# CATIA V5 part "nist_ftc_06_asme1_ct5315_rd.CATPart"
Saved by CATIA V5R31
Part number: NIST PMI FTC 06 ASME1
Revision: D
Description: NIST PMI test model downloaded from http://go.usa.gov/mGVm
Bounding box of the stored display mesh (mm): x -152.4 to 152.4, y 0 to 97.79, z -247.65 to 0
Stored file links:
  E:\users\dgn\TPS V5\Import-export annotations\Step\PMI representation 2015\NIST UC\FTC\SFA results - 21x export\nist_ftc_06_asme1_ct5315_rd.CATPart
  E:\users\dgn\TPS V5\Import-export annotations\Step\PMI representation 2015\NIST UC\nist_ftc_06_asme1_ct5240_rd.CATPart
  E:\users\dgn\TPS V5\Import-export annotations\Step\PMI representation 2015\NIST UC\CVDHoleParallelCountersink_1_TAG.CATPart
  E:\users\dgn\TPS V5\Import-export annotations\Step\PMI representation 2015\NIST UC\TS_CounterboredHole.CATPart
  E:\Download\DownloadOfCXR31rel\win_b64\resources\graphic\CATTPSGeneralTolerance.xlsx
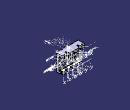
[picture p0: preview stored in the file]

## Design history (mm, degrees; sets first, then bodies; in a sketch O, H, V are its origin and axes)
TTRSSet1
f4a2d38f3ddc11d3a929006094b99c4b_11 "CATTPSSet"
Set1 "Geom_for_MBD_A_notes"
  Plane1: type Equation, A -0.57735, B -0.57735, C 0.57735, Length 229.55, RefPoint vertex [face of Pad1 from Sketch12.L1 | face of Pad1 from Sketch12.L2 | end face of Pad1], RefAxis AxisSystem5
Set2 "MBD_A"
  AxisSystem1 "F1": origin (108.585, 50.8, -209.55), X (-1, 0, 0), Y (0, 1, 0), Z (0, 0, -1)
  AxisSystem2 "F2": origin (36.195, 50.8, -209.55), X (-1, 0, 0), Y (0, 1, 0), Z (0, 0, -1)
  AxisSystem3 "F3": origin (-36.195, 50.8, -209.55), X (-1, 0, 0), Y (0, 1, 0), Z (0, 0, -1)
  AxisSystem4 "F4": origin (-108.585, 50.8, -209.55), X (-1, 0, 0), Y (0, 1, 0), Z (0, 0, -1)
  AxisSystem5 "EAB": origin (0, 0, -209.55), X (-1, 0, 0), Y (0, 0, 1), Z (0, 1, 0)
Set3 "MBD_C"
  AxisSystem6 "DCJ": origin (82.55, 31.75, 0), X (1, 0, 0), Y (0, 0, -1), Z (0, 1, 0)
  AxisSystem7 "DCK": origin (-82.55, 31.75, 0), X (1, 0, 0), Y (0, 0, -1), Z (0, 1, 0)
  AxisSystem8 "DG": origin (76.2, 31.75, -158.75), X (0, 0, -1), Y (-1, 0, 0), Z (0, 1, 0)
  AxisSystem9 "DH": origin (-76.2, 31.75, -158.75), X (0, 0, -1), Y (-1, 0, 0), Z (0, 1, 0)
  Sketch1 on face of Pocket1 from Sketch15.L6, origin (-87.885, 40.9814, 0), H (-0.4226, -0.9063, 0), V (0, 0, 1)
    line L1 (-45.8598, -31.75) -> (-45.8598, 0)
    point P1 (-45.8598, -31.75)
    reference projected point E1 (-45.8598, -31.75) from Sketch10.P5
    vertical: L1 V
    coincidence: P1 E1
  Sketch2 on face of RectPattern2, origin (87.885, 40.9814, 0), H (-0.4226, 0.9063, 0), V (0, 0, 1)
    line L1 (45.8598, -31.75) -> (45.8598, 0)
    point P1 (45.8598, -31.75)
    reference projected point E1 (45.8598, -31.75) from Sketch9.P6
    vertical: L1 V
    coincidence: P1 E1
  Sketch3 on face of RectPattern2, origin (47.7271, -22.2555, 0), H (-0.4226, -0.9063, 0), V (0, 0, 1)
    line L1 (-115.6341, -31.75) -> (-115.6341, 0)
    point P1 (-115.6341, -31.75)
    reference projected point E1 (-115.6341, -31.75) from Sketch9.P5
    vertical: L1 V
    coincidence: P1 E1
  Sketch4 on Plane6, origin (0, 66.04, 0), H (-1, 0, 0), V (0, 0, 1)
    circle A1 centre (76.2, -158.75) radius 12.7
    point P1 (76.2, -158.75)
    reference projected point E1 (76.2, -158.75) from axis of face of RectPattern6
    circle A2 centre (-76.2, -158.75) radius 12.7
    point P2 (-76.2, -158.75)
    reference projected point E2 (-76.2, -158.75) from axis of face of Hole3
    radius A1 = 12.7
    radius A2 = 12.7
    coincidence: E1 P1, E2 P2
  Sketch5 on face of RectPattern2, origin (47.7271, -22.2555, 0), H (-0.4226, -0.9063, 0), V (0, 0, 1)
    projected line E1 (-132.4556, 0) -> (-97.4233, 0) from edge [face of RectPattern2 | face of Pad1 from Sketch12.L1]
    projected line E2 (-132.4556, -31.75) -> (-97.4233, -31.75) from edge [face of Pad1 from Sketch12.L7 | face of RectPattern2]
    line L1 (-97.4233, 0) -> (-115.6341, 0)
    point P5 (-114.9395, 0)
    line L2 (-115.6341, -31.75) -> (-97.4233, -31.75)
    point P6 (-115.6341, -31.75)
    line L3 (-97.4233, 0) -> (-97.4233, -31.75)
    line L4 (-115.6341, 0) -> (-115.6341, -31.75)
    reference projected line E3 (-115.6341, -31.75) -> (-115.6341, 0) from Sketch3
    midpoint: P5 E1
    horizontal: L1 H, L2 H
    coincidence: P6 E2, E3 L4
    vertical: L3 V, L4 V
  Sketch6 on face of RectPattern2, origin (87.885, 40.9814, 0), H (-0.4226, 0.9063, 0), V (0, 0, 1)
    projected line E1 (62.6813, 0) -> (27.6491, 0) from edge [face of Pad1 from Sketch12.L1 | face of RectPattern2]
    projected line E2 (45.8598, 0) -> (27.6491, 0) from edge [face of Pad1 from Sketch12.L1 | face of RectPattern2]
    projected line E3 (27.6491, -31.75) -> (27.6491, 0) from edge [face of RectPattern2 | face of RectPattern2]
    projected line E4 (27.6491, -31.75) -> (62.6813, -31.75) from edge [face of Pad1 from Sketch12.L7 | face of RectPattern2]
    projected line E5 (27.6491, -31.75) -> (45.8598, -31.75) from edge [face of Pad1 from Sketch12.L7 | face of RectPattern2]
    projected line E6 (45.8598, -31.75) -> (45.8598, 0) from Sketch2.L1
  Sketch7 on face of Pocket1 from Sketch15.L6, origin (-87.885, 40.9814, 0), H (-0.4226, -0.9063, 0), V (0, 0, 1)
    projected line E1 (-62.6813, 0) -> (-27.6491, 0) from edge [face of Pocket1 from Sketch15.L6 | face of Pad1 from Sketch12.L1]
    projected line E2 (-45.8598, 0) -> (-27.6491, 0) from edge [face of Pocket1 from Sketch15.L6 | face of Pad1 from Sketch12.L1]
    projected line E3 (-62.6813, -31.75) -> (-27.6491, -31.75) from edge [face of Pad1 from Sketch12.L7 | face of Pocket1 from Sketch15.L6]
    projected line E4 (-45.8598, -31.75) -> (-27.6491, -31.75) from edge [face of Pad1 from Sketch12.L7 | face of Pocket1 from Sketch15.L6]
    projected line E5 (-27.6491, -31.75) -> (-27.6491, 0) from edge [face of Pocket1 from Sketch15.L5 | face of Pocket1 from Sketch15.L6]
    projected line E6 (-45.8598, -31.75) -> (-45.8598, 0) from Sketch1.L1
  Sketch8 on face of Pocket1 from Sketch15.L1, origin (-47.7271, -22.2555, 0), H (-0.4226, 0.9063, 0), V (0, 0, 1)
    projected line E1 (97.4233, -31.75) -> (132.4556, -31.75) from edge [face of Pad1 from Sketch12.L7 | face of Pocket1 from Sketch15.L1]
    projected line E2 (97.4233, -31.75) -> (115.6341, -31.75) from edge [face of Pad1 from Sketch12.L7 | face of Pocket1 from Sketch15.L1]
    projected line E3 (97.4233, -31.75) -> (97.4233, 0) from edge [face of Pocket1 from Sketch15.L1 | face of Pocket1 from Sketch15.L2]
    projected line E4 (132.4556, 0) -> (97.4233, 0) from edge [face of Pad1 from Sketch12.L1 | face of Pocket1 from Sketch15.L1]
    projected line E5 (115.6341, 0) -> (97.4233, 0) from edge [face of Pad1 from Sketch12.L1 | face of Pocket1 from Sketch15.L1]
    projected line E6 (115.6341, -31.75) -> (115.6341, 0) from Sketch11.L1
    construction line L1 through (0, 0) direction (0, 1)
  Sketch9 on face of Pad1 from Sketch12.L7, origin (0, 0, -31.75), H (1, 0, 0), V (0, -1, 0)
    projected line E1 (103.7053, -97.79) -> (88.9, -66.04) from edge [face of Pad1 from Sketch12.L7 | face of RectPattern2]
    projected line E2 (76.2, -66.04) -> (61.3947, -97.79) from edge [face of Pad1 from Sketch12.L7 | face of RectPattern2]
    line L1 (88.9, -66.04) -> (76.2, -66.04)
    line L2 (96.5962, -82.5446) -> (68.5038, -82.5446)
    point P5 (96.5962, -82.5446)
    point P6 (68.5038, -82.5446)
    point P7 (96.5962, -82.5446)
    point P8 (68.5038, -82.5446)
    length L2 = 28.0924
    horizontal: L1 H, L2 H
    coincidence: P5 E1, P6 E2, P7 P5, P8 P6
  Sketch10 on face of Pad1 from Sketch12.L7, origin (0, 0, -31.75), H (1, 0, 0), V (0, -1, 0)
    projected line E1 (-61.3947, -97.79) -> (-76.2, -66.04) from edge [face of Pad1 from Sketch12.L7 | face of Pocket1 from Sketch15.L6]
    projected line E2 (-88.9, -66.04) -> (-103.7053, -97.79) from edge [face of Pad1 from Sketch12.L7 | face of Pocket1 from Sketch15.L1]
    line L1 (-76.2, -66.04) -> (-88.9, -66.04)
    line L2 (-68.5038, -82.5446) -> (-96.5962, -82.5446)
    point P5 (-68.5038, -82.5446)
    point P6 (-96.5962, -82.5446)
    point P7 (-68.5038, -82.5446)
    point P8 (-96.5962, -82.5446)
    length L2 = 28.0924
    horizontal: L1 H, L2 H
    coincidence: P5 E1, P7 P5, P6 E2, P8 P6
  Sketch11 on face of Pocket1 from Sketch15.L1, origin (-47.7271, -22.2555, 0), H (-0.4226, 0.9063, 0), V (0, 0, 1)
    line L1 (115.6341, -31.75) -> (115.6341, 0)
    point P1 (115.6341, -31.75)
    reference projected point E1 (115.6341, -31.75) from Sketch10.P6
    vertical: L1 V
    coincidence: P1 E1
  Line1 to Line4: stored without definition
Set4 "MBD_A_B_C"
  AxisSystem10 "DBC": origin (0, 31.75, 0), X (1, 0, 0), Y (0, 0, -1), Z (0, 1, 0)
  AxisSystem11 "ABC": origin (0, 0, 0), X (1, 0, 0), Y (0, 0, -1), Z (0, 1, 0)
Set5
  Plane2: type Offset, RefPlane xy-plane, Offset 247.65, reversed
  Plane3: type Offset, RefPlane zx-plane, Offset 46.99
  Plane4: type Offset, RefPlane yz-plane, Offset 76.2
  Plane5: type Offset, RefPlane yz-plane, Offset 114.3
  Point1: type OnCurve, Support edge [face of Pad1 from Sketch12.L7 | face of Pocket1 from Sketch15.L1], Length 18.2093
  Point2: type OnCurve, Support edge [face of Pad1 from Sketch12.L7 | face of Pocket1 from Sketch15.L6], Length 18.2093
  Point3: type OnCurve, Support edge [face of Pad1 from Sketch12.L7 | face of RectPattern2], Length 18.2093
  Point4: type OnCurve, Support edge [face of Pad1 from Sketch12.L7 | face of RectPattern2], Length 18.2093
  Plane6: type Offset, RefPlane zx-plane, Offset 66.04
  Plane7: type Angle, RefPlane xy-plane, Direction edge [face of Pad1 from Sketch12.L2 | face of Pad1 from Sketch12.L1], Angle 45
  Point5: type OnCurve, Support edge [face of Pad1 from Sketch12.L2 | face of Pad1 from Sketch12.L1], Length 152.4
  Point6: type OnPlane, Support face of Pad1 from Sketch12.L6, H 0, V 0, Direction (-1, 0, 0)
  Point7: type OnCurve, Support edge [face of Fillet1 | face of Pad1 from Sketch12.L6], RefPoint {extremum Reference edge [face of Fillet1 | face of Pad1 from Sketch12.L6], Direction (1, 2, 3)}, Length 65.977
  Point8: type OnCurve, Support edge [face of Fillet1 | face of Pad1 from Sketch12.L6], RefPoint {extremum Reference edge [face of Fillet1 | face of Pad1 from Sketch12.L6], Direction (1, 2, 3)}, Length 65.9892
  Point9: type OnPlane, Support face of Pad1 from Sketch12.L1, H 82.55, V 31.75, Direction (1, 0, 0)
  Point10: type OnPlane, Support face of Pad1 from Sketch12.L1, H -82.55, V 31.75, Direction (1, 0, 0)
  Plane8: type Offset, RefPlane face of Pad1 from Sketch12.L2, Offset 82.55
  Plane9: type Offset, RefPlane face of Pad1 from Sketch12.L2, Offset 66.04
  Point11: type OnSurface, Support face of Fillet1, Length 0, Direction (-0.9567, 0.021, -0.2904)
  Plane10: type Offset, RefPlane face of Pad1 from Sketch12.L1, Offset 107.95
  Point12: type OnPlane, Support face of Pad1 from Sketch12.L6, H -76.2, V -158.75, Direction (-1, 0, 0)
  Point13: type OnPlane, Support face of Pad1 from Sketch12.L6, H 76.2, V -158.75, Direction (-1, 0, 0)
  Point14: type OnPlane, Support face of Pad1 from Sketch12.L2, H 0, V -209.55, Direction (1, 0, 0)
  Plane11: type Offset, RefPlane face of Pad1 from Sketch12.L8, Offset 0, reversed
  Point15 to Point18: stored without definition
Body1 (main body)
  Sketch12 on yz-plane, origin (0, 0, 0), H (0, 1, 0), V (0, 0, 1)
    point P1 (97.79, 0)
    line L1 (97.79, 0) -> (0, 0)
    line L2 (0, 0) -> (0, -234.95)
    line L3 (0, -234.95) -> (50.8, -234.95)
    line L4 (50.8, -234.95) -> (50.8, -209.55)
    line L5 (50.8, -209.55) -> (31.75, -209.55)
    line L6 (31.75, -209.55) -> (31.75, -31.75)
    line L7 (31.75, -31.75) -> (97.79, -31.75)
    line L8 (97.79, -31.75) -> (97.79, 0)
    length L2 = 234.95
    distance L1 L5 = 209.55
    distance L1 L7 = 31.75
    distance L2 L6 = 31.75
    distance L4 L2 = 50.8
    distance L2 L8 = 97.79
    coincidence: P1 H
    horizontal: L1 H, L3 H, L5 H, L7 H
    vertical: L2 V, L4 V, L6 V, L8 V
  Pad1: profile Sketch12, direction (1, 0, 0), length 152.4, mirrored extent
  Sketch13 on yz-plane, origin (0, 0, 0), H (0, 1, 0), V (0, 0, 1)
    line L1 (97.79, -31.75) -> (46.99, -133.35)
    point P1 (97.79, -31.75)
    point P2 (46.99, -133.35)
    line L2 (46.99, -133.35) -> (31.75, -133.35)
    point P3 (31.75, -133.35)
    reference projected point E1 (97.79, -31.75) from vertex [face of Pad1 from Sketch12.L8 | end face of Pad1 | face of Pad1 from Sketch12.L7]
    reference projected point E2 (97.79, -31.75) from vertex [face of Pad1 from Sketch12.L8 | end face of Pad1 | face of Pad1 from Sketch12.L7]
    reference projected line E3 (31.75, -31.75) -> (97.79, -31.75) from edge [face of Pad1 from Sketch12.L7 | end face of Pad1]
    reference projected line E4 (97.79, -31.75) -> (97.79, 0) from edge [face of Pad1 from Sketch12.L8 | end face of Pad1]
    reference intersected line E5 (31.75, -31.75) -> (31.75, -209.55) from face of Pad1 from Sketch12.L6
    distance E3 L2 = 101.6
    distance P2 E4 = 50.8
    coincidence: E1 L1, E2 P1, E5 P3
  Stiffener1: ExtendedProfile Sketch13, ThicknessTop 0, ThicknessValue 25.4
  Sketch14 on Plane2, origin (0, 0, -247.65), H (1, 0, 0), V (0, 1, 0)
    circle A1 centre (108.585, 50.8) radius 22.225
    point P1 (108.585, 50.8)
    reference projected line E1 (-152.4, 0) -> (152.4, 0) from edge [face of Pad1 from Sketch12.L3 | face of Pad1 from Sketch12.L2]
    reference intersected line E2 through (152.4, 0) direction (0, 1) from end face of Pad1
    distance P1 E1 = 50.8
    radius A1 = 22.225
    distance E2 P1 = 43.815
  Pad2: profile Sketch14, direction (0, 0, 1), length 38.1
  RectPattern1: of Pad2, direction 1 instances 4, spacing 72.39, along edge [face of Pad1 from Sketch12.L4 | face of Pad1 from Sketch12.L3] reversed
  Sketch15 on face of Pad1 from Sketch12.L7, origin (0, 0, -31.75), H (1, 0, 0), V (0, -1, 0)
    line L1 (-103.7053, -97.79) -> (-88.9, -66.04)
    point P1 (-88.9, -66.04)
    line L2 (-88.9, -66.04) -> (-88.9, -52.07)
    line L3 (-88.9, -52.07) -> (-76.2, -52.07)
    reference intersected line E1 (-152.4, 0) -> (152.4, 0) from face of Pad1 from Sketch12.L2
    axis line L4 (-82.55, -52.07) -> (-82.55, -133.5251)
    reference intersected line E2 (-152.4, 0) -> (152.4, 0) from face of Pad1 from Sketch12.L2
    point P7 (-76.2, -66.04)
    line L5 (-76.2, -66.04) -> (-76.2, -52.07)
    line L6 (-61.3947, -97.79) -> (-76.2, -66.04)
    reference intersected line E3 through (0, 0) direction (0, 1) from yz-plane
    projected line E4 (-152.4, -97.79) -> (-12.7, -97.79) from edge [face of Pad1 from Sketch12.L8 | face of Pad1 from Sketch12.L7]
    projected line E5 (-103.7053, -97.79) -> (-61.3947, -97.79) from edge [face of Pad1 from Sketch12.L8 | face of Pad1 from Sketch12.L7]
    distance E1 L3 = 52.07
    length L3 = 12.7
    distance L2 L4 = 6.35
    distance E2 P1 = 66.04
    distance E2 P7 = 66.04
    distance L5 L4 = 6.35
    angle L1 L6 = 50
    distance E3 L4 = 82.55
    angle L1 L4 = 25
  Pocket1: profile Sketch15, direction (0, 0, 1), through (limit type 6)
  RectPattern2: of Pocket1, direction 1 instances 2, spacing 165.1, along edge [face of Pad1 from Sketch12.L8 | face of Pad1 from Sketch12.L7]
  Sketch16 on Plane3, origin (0, 46.99, 0), H (0, 0, 1), V (1, 0, 0)
    circle A1 centre (-158.75, 76.2) radius 15.875
    point P1 (-158.75, 76.2)
    reference projected line E1 (0, -152.4) -> (0, 152.4) from edge [face of Pad1 from Sketch12.L1 | face of Pad1 from Sketch12.L8]
    reference intersected line E2 through (0, 0) direction (-1, 0) from yz-plane
    radius A1 = 15.875
    distance E1 P1 = 158.75
    distance E2 P1 = 76.2
  Pad3: profile Sketch16, direction (0, -1, 0), up to face of Pad1 from Sketch12.L6
  Sketch17 on Plane4, origin (76.2, 0, 0), H (0, 1, 0), V (0, 0, 1)
    axis line L1 (47.3647, -158.75) -> (174.207, -158.75)
    reference intersected line E1 (0, 0) -> (97.79, 0) from face of Pad1 from Sketch12.L1
    point P3 (46.99, -174.625)
    line L2 (46.99, -174.625) -> (85.09, -168.275)
    line L3 (85.09, -168.275) -> (85.09, -158.75)
    line L4 (85.09, -158.75) -> (46.99, -158.75)
    reference intersected line E2 (0, -234.95) -> (0, 0) from face of Pad1 from Sketch12.L2
    projected line E3 (46.99, -142.875) -> (46.99, -174.625) from edge [face of Pad3 from Sketch16.A1 | start face of Pad3]
    projected line E4 (46.99, -158.75) -> (46.99, -174.625) from edge [face of Pad3 from Sketch16.A1 | start face of Pad3]
    point P7 (46.99, -174.625)
    distance E1 L1 = 158.75
    distance L3 E2 = 85.09
    length L3 = 9.525
    coincidence: P3 P7, L1 L4
  Shaft1: profile Sketch17, axis Sketch17.L1, angle 360
  Sketch18 on Plane5, origin (114.3, 0, 0), H (0, 1, 0), V (0, 0, 1)
    axis line L1 (-156.5, -107.95) -> (163.5, -107.95)
    arc A1 centre (63.5, -107.95) radius 15.875 from (79.375, -107.95) to (47.625, -107.95) ccw
    point P3 (63.5, -107.95)
    reference projected line E1 (97.79, 0) -> (0, 0) from edge [face of Pad1 from Sketch12.L1 | end face of Pad1]
    reference projected line E2 (0, 0) -> (0, -234.95) from edge [face of Pad1 from Sketch12.L2 | end face of Pad1]
    distance P3 E1 = 107.95
    distance E2 P3 = 63.5
    radius A1 = 15.875
    coincidence: P3 L1
  Shaft2: profile Sketch18, axis Sketch18.L1, angle 360
  Sketch19 on face of Pad1 from Sketch12.L6, origin (0, 31.75, 0), H (-1, 0, 0), V (0, 0, 1)
    circle A1 centre (-114.3, -107.95) radius 11.43
    point P1 (-114.3, -107.95)
    reference intersected line E1 (-152.4, 0) -> (152.4, 0) from face of Pad1 from Sketch12.L1
    reference intersected line E2 through (0, 0) direction (0, -1) from yz-plane
    distance P1 E1 = 107.95
    distance P1 E2 = 114.3
    radius A1 = 11.43
  Pad4: profile Sketch19, direction (0, 1, 0), up to face of Shaft2 from Sketch18.A1
  Sketch20 on face of Pad1 from Sketch12.L7, origin (129.0197, 80.9562, -31.75), H (1, 0, 0), V (0, -1, 0)
    point P1 (-2.0197, 2.2162)
    reference intersected line E1 through (-129.0197, 0) direction (0, 1) from yz-plane
    reference intersected line E2 (23.3803, -16.8338) -> (-281.4197, -16.8338) from face of Pad1 from Sketch12.L8
    distance E1 P1 = 127
    distance P1 E2 = 19.05
  Hole1: placed by Sketch20, at (127, 78.74, -31.75) direction (0, 0, 1), diameter 14.2875, through (limit type 6), counterbore diameter 20.6375, counterbore depth 14.2875
  RectPattern3: of Hole1, direction 1 instances 2, spacing 254, along edge [face of Pad1 from Sketch12.L8 | face of Pad1 from Sketch12.L7] reversed
  Sketch21 on face of Pad1 from Sketch12.L6, origin (123.0782, 31.75, -62.8696), H (1, 0, 0), V (0, 0, -1)
    point P1 (10.2718, -5.7196)
    reference projected line E1 (-275.4782, -62.8696) -> (29.3218, -62.8696) from edge [face of Pad1 from Sketch12.L1 | face of Pad1 from Sketch12.L8]
    reference intersected line E2 through (-123.0782, 0) direction (0, 1) from yz-plane
    distance E1 P1 = 57.15
    distance E2 P1 = 133.35
  Hole2: placed by Sketch21, at (133.35, 31.75, -57.15) direction (0, -1, 0), diameter 10.541, through (limit type 6), counterbore diameter 15.875, counterbore depth 12.7
  RectPattern4: of Hole2, direction 1 instances 2, spacing 266.7, along edge [face of Pad1 from Sketch12.L8 | face of Pad1 from Sketch12.L7] reversed, direction 2 instances 2, spacing 127, along edge [face of Pad1 from Sketch12.L6 | end face of Pad1] reversed
  RectPattern5: of Pad3, Sketch16, Shaft1, Sketch17, direction 1 instances 2, spacing 152.4, along edge [face of Pad1 from Sketch12.L8 | face of Pad1 from Sketch12.L7] reversed, direction 2 instances 2, spacing 127
  Sketch22 on face of Shaft1 from Sketch17.L3, origin (76.2, 85.09, -158.75), H (1, 0, 0), V (0, 0, -1)
    point P1 (0, 0)
    coincidence: P1 O
  Hole3: placed by Sketch22, at (76.2, 85.09, -158.75) direction (0, -1, 0), diameter 6.35, depth 12.7, V-bottom angle 118
  RectPattern6: of Hole3, direction 1 instances 2, spacing 152.4, along edge [face of Pad1 from Sketch12.L4 | face of Pad1 from Sketch12.L3] reversed, direction 2 instances 2, spacing 127
  Fillet1: radius 3.175, on edge [face of Pad1 from Sketch12.L7 | face of Pad1 from Sketch12.L6] (x2); edge [face of Stiffener1 | face of Pad1 from Sketch12.L7]; edge [face of Pad1 from Sketch12.L6 | face of Stiffener1]; edge [face of Stiffener1 from Sketch13.L2 | face of Pad1 from Sketch12.L6]; edge [face of Stiffener1 | face of Pad1 from Sketch12.L6]; edge [face of Pad1 from Sketch12.L7 | face of Stiffener1]; edge [face of Pad1 from Sketch12.L6 | face of RectPattern5]; edge [face of Pad1 from Sketch12.L6 | face of Pad3 from Sketch16.A1]; edge [face of Pad1 from Sketch12.L6 | face of RectPattern1]; edge [face of Pad1 from Sketch12.L4 | face of Pad2 from Sketch14.A1]; edge [face of Pad2 from Sketch14.A1 | face of Pad1 from Sketch12.L4]; edge [face of RectPattern1 | face of Pad1 from Sketch12.L4] (x3); edge [face of Pad1 from Sketch12.L4 | face of RectPattern1] (x3)
  Sketch23 on face of Pad1 from Sketch12.L8, origin (0, 97.79, 0), H (-1, 0, 0), V (0, 0, 1)
    arc A1 centre (0, -15.875) radius 12.7 from (0, -28.575) to (0, -3.175) ccw
    point P1 (0, -15.875)
    reference intersected line E1 through (0, 0) direction (0, -1) from yz-plane
    reference intersected line E2 (152.4, -31.75) -> (-152.4, -31.75) from face of Pad1 from Sketch12.L7
    line L1 (0, -3.175) -> (0, -28.575)
    radius A1 = 12.7
    distance E2 P1 = 15.875
    coincidence: E1 P1, P1 L1
    vertical: L1 V
  Fillet2: radius 12.7, on edge [start face of Pad1 | face of Pad1 from Sketch12.L8]; edge [face of Pad1 from Sketch12.L8 | end face of Pad1]
  Groove1: profile Sketch23, axis Sketch23.L1, angle 360
  Sketch24 on Plane10, origin (0, 97.79, -107.95), H (0, 1, 0), V (1, 0, 0)
    line L1 (-66.04, -114.3) -> (-18.415, -114.3)
    point P1 (-162.8215, -114.3)
    point P2 (-2.54, -114.3)
    line L2 (-66.04, -114.3) -> (-66.04, -125.73)
    line L3 (-66.04, -125.73) -> (-45.3068, -125.73)
    arc A1 centre (-34.29, -114.3) radius 15.875 from (-45.3068, -125.73) to (-18.415, -114.3) ccw
    point P5 (-34.29, -114.3)
    reference intersected line E1 (-66.04, 152.4) -> (-66.04, -152.4) from face of Pad1 from Sketch12.L6
    reference intersected line E2 through (0, 0) direction (-1, 0) from yz-plane
    reference intersected line E3 (-97.79, -152.4) -> (-97.79, 152.4) from face of Pad1 from Sketch12.L2
    radius A1 = 15.875
    distance E2 L1 = 114.3
    distance L1 L3 = 11.43
    distance P5 E3 = 63.5
    horizontal: L1 H, L3 H
    vertical: L2 V
    coincidence: E1 L2, P1 L1, L1 P5
  Shaft3: profile Sketch24, axis Sketch24.L1, angle 360
  Fillet3: radius 3.175, on edge [face of Pad4 from Sketch19.A1 | face of Shaft2 from Sketch18.A1]; edge [face of Pad1 from Sketch12.L6 | face of Pad4 from Sketch19.A1]
  Fillet4: radius 3.175, on edge [face of Shaft3 from Sketch24.A1 | face of Shaft3 from Sketch24.L3]; edge [face of Shaft3 from Sketch24.L3 | face of Pad1 from Sketch12.L6]
  Sketch25 "Main View" on face of Pad1 from Sketch12.L3, origin (0, 0, -234.95), H (-1, 0, 0), V (0, 1, 0)
    point P1 (-27.9401, 6.35)
    point P2 (-14.4332, 7.6694)
    point P3 (-8.1701, 9.8671)
    point P4 (-3.0267, 10.5457)
    point P5 (-1.9341, 9.4532)
    point P6 (-24.8376, 6.35)
    point P7 (-27.9401, 6.35)
    point P8 (-24.8376, 17.5935)
    point P9 (-24.8376, 6.35)
    point P10 (-23.9004, 17.959)
    point P11 (-24.8376, 17.5935)
    point P12 (-14.4332, 7.6694)
    point P13 (-23.9004, 17.959)
    point P14 (-8.1701, 21.35)
    point P15 (-8.1701, 9.8671)
    point P16 (-11.3024, 21.35)
    point P17 (-8.1701, 21.35)
    point P18 (-11.3024, 9.9419)
    point P19 (-11.3024, 21.35)
    point P20 (-12.02, 9.6257)
    point P21 (-11.3024, 9.9419)
    point P22 (-22.2849, 20.7261)
    point P23 (-12.02, 9.6257)
    point P24 (-22.2849, 20.7261)
    point P25 (-27.9401, 18.5121)
    point P26 (-27.9401, 6.35)
    point P27 (-27.9401, 18.5121)
    point P28 (-3.0267, 21.35)
    point P29 (-6.159, 21.35)
    point P30 (-3.0267, 10.5457)
    point P31 (-3.0267, 21.35)
    point P32 (12.7773, 9.4532)
    point P33 (-1.9341, 9.4532)
    point P34 (12.7773, 9.4532)
    point P35 (12.7198, 12.2696)
    point P36 (3.668, 12.2696)
    point P37 (12.7198, 12.2696)
    point P38 (3.3241, 21.35)
    point P39 (3.668, 12.2696)
    point P40 (28.9273, 21.35)
    point P41 (3.3241, 21.35)
    point P42 (28.9273, 18.189)
    point P43 (28.9273, 21.35)
    point P44 (22.5181, 18.189)
    point P45 (28.9273, 18.189)
    point P46 (22.5181, 6.35)
    point P47 (22.5181, 18.189)
    point P48 (19.4156, 6.35)
    point P49 (22.5181, 6.35)
    point P50 (19.4156, 18.189)
    point P51 (19.4156, 6.35)
    point P52 (3.7255, 18.189)
    point P53 (19.4156, 18.189)
    point P54 (3.7255, 18.189)
    point P55 (3.6105, 15.3729)
    point P56 (13.2373, 15.3729)
    point P57 (3.6105, 15.3729)
    point P58 (13.2373, 6.35)
    point P59 (13.2373, 15.3729)
    point P60 (-1.9632, 6.35)
    point P61 (13.2373, 6.35)
    point P62 (-6.159, 10.5457)
    point P63 (-1.9632, 6.35)
    point P64 (-6.159, 21.35)
    point P65 (-6.159, 10.5457)
    line L1 (-6.159, 21.35) -> (-6.159, 10.5457)
    arc A1 centre (-1.9632, 10.5457) radius 4.1957 from (-6.159, 10.5457) to (-1.9632, 6.35) ccw
    line L2 (-1.9632, 6.35) -> (13.2373, 6.35)
    arc A2 centre (12.5188, 10.8615) radius 4.5683 from (13.2373, 6.35) to (13.2373, 15.3729) ccw
    line L3 (13.2373, 15.3729) -> (3.6105, 15.3729)
    arc A3 centre (3.6105, 16.7833) radius 1.4104 from (3.7255, 18.189) to (3.6105, 15.3729) ccw
    line L4 (3.7255, 18.189) -> (19.4156, 18.189)
    line L5 (19.4156, 18.189) -> (19.4156, 6.35)
    line L6 (19.4156, 6.35) -> (22.5181, 6.35)
    line L7 (22.5181, 6.35) -> (22.5181, 18.189)
    line L8 (22.5181, 18.189) -> (28.9273, 18.189)
    line L9 (28.9273, 18.189) -> (28.9273, 21.35)
    line L10 (28.9273, 21.35) -> (3.3241, 21.35)
    arc A4 centre (3.3241, 16.8033) radius 4.5467 from (3.3241, 21.35) to (3.668, 12.2696) ccw
    line L11 (3.668, 12.2696) -> (12.7198, 12.2696)
    arc A5 centre (12.5971, 10.8583) radius 1.4166 from (12.7773, 9.4532) to (12.7198, 12.2696) ccw
    line L12 (12.7773, 9.4532) -> (-1.9341, 9.4532)
    line L13 (-3.0267, 10.5457) -> (-3.0267, 21.35)
    line L14 (-3.0267, 21.35) -> (-6.159, 21.35)
    line L15 (-27.9401, 6.35) -> (-27.9401, 18.5121)
    arc A6 centre (-24.6791, 18.5121) radius 3.261 from (-22.2849, 20.7261) to (-27.9401, 18.5121) ccw
    line L16 (-22.2849, 20.7261) -> (-12.02, 9.6257)
    arc A7 centre (-11.7156, 9.9072) radius 0.4146 from (-12.02, 9.6257) to (-11.3024, 9.9419) ccw
    line L17 (-11.3024, 9.9419) -> (-11.3024, 21.35)
    line L18 (-11.3024, 21.35) -> (-8.1701, 21.35)
    line L19 (-8.1701, 21.35) -> (-8.1701, 9.8671)
    line L20 (-14.4332, 7.6694) -> (-23.9004, 17.959)
    arc A8 centre (-24.2977, 17.5935) radius 0.5399 from (-23.9004, 17.959) to (-24.8376, 17.5935) ccw
    line L21 (-24.8376, 17.5935) -> (-24.8376, 6.35)
    line L22 (-24.8376, 6.35) -> (-27.9401, 6.35)
    arc A9 centre (-1.9341, 10.5457) radius 1.0926 from (-3.0267, 10.5457) to (-1.9341, 9.4532) ccw
    arc A10 centre (-11.6873, 9.8671) radius 3.5171 from (-14.4332, 7.6694) to (-8.1701, 9.8671) ccw
    distance P1 H = 6.35
    distance P1 V = 27.94
    fix: P2, P3, P4, P5, P6, P8, P9, P10, P11, P12, P13, P14, P15, P16, P17, P18, P19, P20, P21, P22, P23, P24, P25, P27, P28, P29, P30, P31, P32, P33, P34, P35, P36, P37, P38, P39, P40, P41, P42, P43, P44, P45, P46, P47, P48, P49, P50, P51, P52, P53, P54, P55, P56, P57, P58, P59, P60, P61, P62, P63, P64, P65, P1, P7, L1, A1, L2, A2, L3, A3, L4, L5, L6, L7, L8, L9, L10, A4, L11, A5, L12, L13, L14, L15, A6, L16, A7, L17, L18, L19, L20, A8, L21, L22, A9, A10, P26
  Pocket2: profile Sketch25, direction (0, 0, 1), length 2.54
  UdfFeature1 "Counterbored Hole": UdfShapeIn Pocket2, UdfInputSpec1 AxisSystem12, UdfInputSpec2 Project1, UdfInputSpec3 Intersect1, DB 7.1374, T 40.64 {= Body2.Offset + (Sketch26.length(L2) * (Body2.Offset / Body2.Offset))}, DFS 10.16, TFS 10.414
  UdfFeature2 "Counterbored Hole": UdfShapeIn UdfFeature1, UdfInputSpec1 AxisSystem14, UdfInputSpec2 Project2, UdfInputSpec3 Intersect2, DB 7.1374, T 40.64 {= Body3.Offset + (Sketch27.length(L2) * (Body3.Offset / Body3.Offset))}, DFS 10.16, TFS 10.414
  UdfFeature3 "Counterbored Hole": UdfShapeIn UdfFeature2, UdfInputSpec1 AxisSystem16, UdfInputSpec2 Project3, UdfInputSpec3 Intersect3, DB 7.1374, T 40.64 {= Body4.Offset + (Sketch28.length(L2) * (Body4.Offset / Body4.Offset))}, DFS 10.16, TFS 10.414
  UdfFeature4 "Counterbored Hole": UdfShapeIn UdfFeature3, UdfInputSpec1 AxisSystem18, UdfInputSpec2 Project4, UdfInputSpec3 Intersect4, DB 7.1374, T 40.64 {= Body5.Offset + (Sketch29.length(L2) * (Body5.Offset / Body5.Offset))}, DFS 10.16, TFS 10.414
Body2 "UDF_Body"
  AxisSystem12 "MainAxisSystem": origin (108.585, 50.8, -250.19), X (-0.9916, -0.1291, 0), Y (-0.1291, 0.9916, 0), Z (0, 0, -1)
  Project1 "Project": ToProject vertex [YZ plane of AxisSystem12 | ZX plane of AxisSystem12 | XY plane of AxisSystem12], Support face of RectPattern1
  Intersect1 "Intersect": ToIntersect1 edge [ZX plane of AxisSystem12 | YZ plane of AxisSystem12], ToIntersect2 face of RectPattern1
  Sketch26 "MainProfileSketch" on ZX plane of AxisSystem12, origin (108.585, 50.8, -250.19), H (0.9916, 0.1291, 0), V (0, 0, -1)
    axis line L1 (0, 0) -> (0, -40.64)
    line L2 (0, -40.64) -> (3.5687, -40.64)
    point P3 (3.5687, -40.64)
    line L3 (3.5687, -40.64) -> (3.5687, -10.414)
    line L4 (5.08, -2) -> (7.08, 0)
    point P4 (7.08, 0)
    line L5 (7.08, 0) -> (7.08, 0)
    line L6 (7.08, 0) -> (7.08, 0)
    line L7 (7.08, 0) -> (0, 0)
    construction line L8 (7.08, 0) -> (0, 0)
    reference projected line E1 through (0, 0) direction (-1, 0) from edge [XY plane of AxisSystem12 | ZX plane of AxisSystem12]
    reference projected line E2 through (0, 0) direction (-1, 0) from edge [XY plane of AxisSystem12 | ZX plane of AxisSystem12]
    reference projected line E3 through (0, 0) direction (0, 1) from edge [ZX plane of AxisSystem12 | YZ plane of AxisSystem12]
    point P7 (-7.08, 0)
    construction line L9 (-11.04, 3.96) -> (-7.08, 0)
    reference projected line E4 through (0, 0) direction (-1, 0) from edge [XY plane of AxisSystem12 | ZX plane of AxisSystem12]
    line L10 (5.08, -10.414) -> (5.08, -2)
    line L11 (3.5687, -10.414) -> (5.08, -10.414)
    arc A1 centre (5.08, -10.414) radius 0 from (5.08, -10.414) to (5.08, -10.414) ccw
    point P9 (5.08, -10.414)
    reference projected line E5 through (0, 0) direction (-1, 0) from edge [XY plane of AxisSystem12 | ZX plane of AxisSystem12]
    construction line L12 (5.08, -10.414) -> (5.08, -10.414)
    construction line L13 (5.08, -10.414) -> (5.08, -10.414)
    point P10 (5.08, -10.414)
    point P11 (5.08, -10.414)
    point P12 (5.08, -10.414)
    line L14 (3.5687, -40.64) -> (3.5687, -40.64)
    point P13 (3.5687, -40.64)
    point P14 (-3.5687, -40.64)
    point P15 (-3.5687, -40.64)
    construction line L15 (-3.5687, -40.64) -> (-3.5687, -40.64)
    point P18 (5.08, -2)
    reference projected line E6 through (0, 0) direction (-1, 0) from edge [XY plane of AxisSystem12 | ZX plane of AxisSystem12]
    point P19 (0, 30)
    angle L4 L9 = 90
    radius about axis L1 L3 = 3.5687 {= Body2.DB / 2}
    distance E1 L2 = 40.64 {= Body2.Offset + (Sketch26.length(L2) * (Body2.Offset / Body2.Offset))}
    length L8 = 7.08 {= sqrt((Body2.AS_H * Body2.AS_H ) + ((Groove2.top_width / 2 + Groove2.AS_ZR ) * (Groove2.top_width / 2 + Groove2.AS_ZR )))}
    angle L8 L5 = 0 {= atan(Body2.AS_H / (Groove2.top_width / 2 + Groove2.AS_ZR ))}
    distance E6 P18 = 2 (reference)
    distance L5 L11 = 10.414
    radius about axis L10 L1 = 5.08 {= Body2.DFS / 2}
    distance E5 P9 = 10.414 {= Body2.TFS - Body2.R}
    radius about axis P9 L1 = 5.08 {= (Body2.DFS / 2) - Body2.R}
    radius A1 = 0 (reference)
    angle L14 L15 = 0
    distance L2 P3 = 0
    length L2 = 3.5687 (reference)
    distance O P19 = 30
    distance P18 P19 V = 32 {= Sketch26.distance(O P19) + Body2.F1}
    coincidence: E4 L5, L1 E3, P11 P10, P12 L11, P19 L1
    perpendicularity: L1 L7, E2 L6, L12 L10, L13 L11
    symmetry: P4 P7 L1, L4 L9 L1, P3 P14 L1, P13 P15 L1, L14 L15 L1
  Groove2 "MainGroove": profile Sketch26, axis Sketch26.L1, angle 360
  Point19 "LimitingAxisSystemOrigin": type OnCurve, Support edge [ZX plane of AxisSystem12 | YZ plane of AxisSystem12], RefPoint Intersect1, Length 0 {= (Sketch26.length(L2)) * (Body2.Offset / Body2.Offset)}
  AxisSystem13 "LimitingAxisSystem": origin (108.585, 50.8, -209.55), X (-0.9916, -0.1291, 0), Y (0.1168, -0.8972, -0.4259), Z (0.055, -0.4224, 0.9048)
Body3 "UDF_Body"
  AxisSystem14 "MainAxisSystem": origin (36.195, 50.8, -250.19), X (-0.9916, -0.1291, 0), Y (-0.1291, 0.9916, 0), Z (0, 0, -1)
  Project2 "Project": ToProject vertex [YZ plane of AxisSystem14 | ZX plane of AxisSystem14 | XY plane of AxisSystem14], Support face of RectPattern1
  Intersect2 "Intersect": ToIntersect1 edge [ZX plane of AxisSystem14 | YZ plane of AxisSystem14], ToIntersect2 face of RectPattern1
  Sketch27 "MainProfileSketch" on ZX plane of AxisSystem14, origin (36.195, 50.8, -250.19), H (0.9916, 0.1291, 0), V (0, 0, -1)
    axis line L1 (0, 0) -> (0, -40.64)
    line L2 (0, -40.64) -> (3.5687, -40.64)
    point P3 (3.5687, -40.64)
    line L3 (3.5687, -40.64) -> (3.5687, -10.414)
    line L4 (5.08, -2) -> (7.08, 0)
    point P4 (7.08, 0)
    line L5 (7.08, 0) -> (7.08, 0)
    line L6 (7.08, 0) -> (7.08, 0)
    line L7 (7.08, 0) -> (0, 0)
    construction line L8 (7.08, 0) -> (0, 0)
    reference projected line E1 through (0, 0) direction (-1, 0) from edge [XY plane of AxisSystem14 | ZX plane of AxisSystem14]
    reference projected line E2 through (0, 0) direction (-1, 0) from edge [XY plane of AxisSystem14 | ZX plane of AxisSystem14]
    reference projected line E3 through (0, 0) direction (0, 1) from edge [ZX plane of AxisSystem14 | YZ plane of AxisSystem14]
    point P7 (-7.08, 0)
    construction line L9 (-11.04, 3.96) -> (-7.08, 0)
    reference projected line E4 through (0, 0) direction (-1, 0) from edge [XY plane of AxisSystem14 | ZX plane of AxisSystem14]
    line L10 (5.08, -10.414) -> (5.08, -2)
    line L11 (3.5687, -10.414) -> (5.08, -10.414)
    arc A1 centre (5.08, -10.414) radius 0 from (5.08, -10.414) to (5.08, -10.414) ccw
    point P9 (5.08, -10.414)
    reference projected line E5 through (0, 0) direction (-1, 0) from edge [XY plane of AxisSystem14 | ZX plane of AxisSystem14]
    construction line L12 (5.08, -10.414) -> (5.08, -10.414)
    construction line L13 (5.08, -10.414) -> (5.08, -10.414)
    point P10 (5.08, -10.414)
    point P11 (5.08, -10.414)
    point P12 (5.08, -10.414)
    line L14 (3.5687, -40.64) -> (3.5687, -40.64)
    point P13 (3.5687, -40.64)
    point P14 (-3.5687, -40.64)
    point P15 (-3.5687, -40.64)
    construction line L15 (-3.5687, -40.64) -> (-3.5687, -40.64)
    point P18 (5.08, -2)
    reference projected line E6 through (0, 0) direction (-1, 0) from edge [XY plane of AxisSystem14 | ZX plane of AxisSystem14]
    point P19 (0, 30)
    angle L4 L9 = 90
    radius about axis L1 L3 = 3.5687 {= Body3.DB / 2}
    distance E1 L2 = 40.64 {= Body3.Offset + (Sketch27.length(L2) * (Body3.Offset / Body3.Offset))}
    length L8 = 7.08 {= sqrt((Body3.AS_H * Body3.AS_H ) + ((Groove3.top_width / 2 + Groove3.AS_ZR ) * (Groove3.top_width / 2 + Groove3.AS_ZR )))}
    angle L8 L5 = 0 {= atan(Body3.AS_H / (Groove3.top_width / 2 + Groove3.AS_ZR ))}
    distance E6 P18 = 2 (reference)
    distance L5 L11 = 10.414
    radius about axis L10 L1 = 5.08 {= Body3.DFS / 2}
    distance E5 P9 = 10.414 {= Body3.TFS - Body3.R}
    radius about axis P9 L1 = 5.08 {= (Body3.DFS / 2) - Body3.R}
    radius A1 = 0 (reference)
    angle L14 L15 = 0
    distance L2 P3 = 0
    length L2 = 3.5687 (reference)
    distance O P19 = 30
    distance P18 P19 V = 32 {= Sketch27.distance(O P19) + Body3.F1}
    coincidence: E4 L5, L1 E3, P11 P10, P12 L11, P19 L1
    perpendicularity: L1 L7, E2 L6, L12 L10, L13 L11
    symmetry: P4 P7 L1, L4 L9 L1, P3 P14 L1, P13 P15 L1, L14 L15 L1
  Groove3 "MainGroove": profile Sketch27, axis Sketch27.L1, angle 360
  Point20 "LimitingAxisSystemOrigin": type OnCurve, Support edge [ZX plane of AxisSystem14 | YZ plane of AxisSystem14], RefPoint Intersect2, Length 0 {= (Sketch27.length(L2)) * (Body3.Offset / Body3.Offset)}
  AxisSystem15 "LimitingAxisSystem": origin (36.195, 50.8, -209.55), X (-0.9916, -0.1291, 0), Y (0.1168, -0.8972, -0.4259), Z (0.055, -0.4224, 0.9048)
Body4 "UDF_Body"
  AxisSystem16 "MainAxisSystem": origin (-36.195, 50.8, -250.19), X (-0.9916, -0.1291, 0), Y (-0.1291, 0.9916, 0), Z (0, 0, -1)
  Project3 "Project": ToProject vertex [YZ plane of AxisSystem16 | ZX plane of AxisSystem16 | XY plane of AxisSystem16], Support face of RectPattern1
  Intersect3 "Intersect": ToIntersect1 edge [ZX plane of AxisSystem16 | YZ plane of AxisSystem16], ToIntersect2 face of RectPattern1
  Sketch28 "MainProfileSketch" on ZX plane of AxisSystem16, origin (-36.195, 50.8, -250.19), H (0.9916, 0.1291, 0), V (0, 0, -1)
    axis line L1 (0, 0) -> (0, -40.64)
    line L2 (0, -40.64) -> (3.5687, -40.64)
    point P3 (3.5687, -40.64)
    line L3 (3.5687, -40.64) -> (3.5687, -10.414)
    line L4 (5.08, -2) -> (7.08, 0)
    point P4 (7.08, 0)
    line L5 (7.08, 0) -> (7.08, 0)
    line L6 (7.08, 0) -> (7.08, 0)
    line L7 (7.08, 0) -> (0, 0)
    construction line L8 (7.08, 0) -> (0, 0)
    reference projected line E1 through (0, 0) direction (-1, 0) from edge [XY plane of AxisSystem16 | ZX plane of AxisSystem16]
    reference projected line E2 through (0, 0) direction (-1, 0) from edge [XY plane of AxisSystem16 | ZX plane of AxisSystem16]
    reference projected line E3 through (0, 0) direction (0, 1) from edge [ZX plane of AxisSystem16 | YZ plane of AxisSystem16]
    point P7 (-7.08, 0)
    construction line L9 (-11.04, 3.96) -> (-7.08, 0)
    reference projected line E4 through (0, 0) direction (-1, 0) from edge [XY plane of AxisSystem16 | ZX plane of AxisSystem16]
    line L10 (5.08, -10.414) -> (5.08, -2)
    line L11 (3.5687, -10.414) -> (5.08, -10.414)
    arc A1 centre (5.08, -10.414) radius 0 from (5.08, -10.414) to (5.08, -10.414) ccw
    point P9 (5.08, -10.414)
    reference projected line E5 through (0, 0) direction (-1, 0) from edge [XY plane of AxisSystem16 | ZX plane of AxisSystem16]
    construction line L12 (5.08, -10.414) -> (5.08, -10.414)
    construction line L13 (5.08, -10.414) -> (5.08, -10.414)
    point P10 (5.08, -10.414)
    point P11 (5.08, -10.414)
    point P12 (5.08, -10.414)
    line L14 (3.5687, -40.64) -> (3.5687, -40.64)
    point P13 (3.5687, -40.64)
    point P14 (-3.5687, -40.64)
    point P15 (-3.5687, -40.64)
    construction line L15 (-3.5687, -40.64) -> (-3.5687, -40.64)
    point P18 (5.08, -2)
    reference projected line E6 through (0, 0) direction (-1, 0) from edge [XY plane of AxisSystem16 | ZX plane of AxisSystem16]
    point P19 (0, 30)
    angle L4 L9 = 90
    radius about axis L1 L3 = 3.5687 {= Body4.DB / 2}
    distance E1 L2 = 40.64 {= Body4.Offset + (Sketch28.length(L2) * (Body4.Offset / Body4.Offset))}
    length L8 = 7.08 {= sqrt((Body4.AS_H * Body4.AS_H ) + ((Groove4.top_width / 2 + Groove4.AS_ZR ) * (Groove4.top_width / 2 + Groove4.AS_ZR )))}
    angle L8 L5 = 0 {= atan(Body4.AS_H / (Groove4.top_width / 2 + Groove4.AS_ZR ))}
    distance E6 P18 = 2 (reference)
    distance L5 L11 = 10.414
    radius about axis L10 L1 = 5.08 {= Body4.DFS / 2}
    distance E5 P9 = 10.414 {= Body4.TFS - Body4.R}
    radius about axis P9 L1 = 5.08 {= (Body4.DFS / 2) - Body4.R}
    radius A1 = 0 (reference)
    angle L14 L15 = 0
    distance L2 P3 = 0
    length L2 = 3.5687 (reference)
    distance O P19 = 30
    distance P18 P19 V = 32 {= Sketch28.distance(O P19) + Body4.F1}
    coincidence: E4 L5, L1 E3, P11 P10, P12 L11, P19 L1
    perpendicularity: L1 L7, E2 L6, L12 L10, L13 L11
    symmetry: P4 P7 L1, L4 L9 L1, P3 P14 L1, P13 P15 L1, L14 L15 L1
  Groove4 "MainGroove": profile Sketch28, axis Sketch28.L1, angle 360
  Point21 "LimitingAxisSystemOrigin": type OnCurve, Support edge [ZX plane of AxisSystem16 | YZ plane of AxisSystem16], RefPoint Intersect3, Length 0 {= (Sketch28.length(L2)) * (Body4.Offset / Body4.Offset)}
  AxisSystem17 "LimitingAxisSystem": origin (-36.195, 50.8, -209.55), X (-0.9916, -0.1291, 0), Y (0.1168, -0.8972, -0.4259), Z (0.055, -0.4224, 0.9048)
Body5 "UDF_Body"
  AxisSystem18 "MainAxisSystem": origin (-108.585, 50.8, -250.19), X (-0.9916, -0.1291, 0), Y (-0.1291, 0.9916, 0), Z (0, 0, -1)
  Project4 "Project": ToProject vertex [YZ plane of AxisSystem18 | ZX plane of AxisSystem18 | XY plane of AxisSystem18], Support face of RectPattern1
  Intersect4 "Intersect": ToIntersect1 edge [ZX plane of AxisSystem18 | YZ plane of AxisSystem18], ToIntersect2 face of RectPattern1
  Sketch29 "MainProfileSketch" on ZX plane of AxisSystem18, origin (-108.585, 50.8, -250.19), H (0.9916, 0.1291, 0), V (0, 0, -1)
    axis line L1 (0, 0) -> (0, -40.64)
    line L2 (0, -40.64) -> (3.5687, -40.64)
    point P3 (3.5687, -40.64)
    line L3 (3.5687, -40.64) -> (3.5687, -10.414)
    line L4 (5.08, -2) -> (7.08, 0)
    point P4 (7.08, 0)
    line L5 (7.08, 0) -> (7.08, 0)
    line L6 (7.08, 0) -> (7.08, 0)
    line L7 (7.08, 0) -> (0, 0)
    construction line L8 (7.08, 0) -> (0, 0)
    reference projected line E1 through (0, 0) direction (-1, 0) from edge [XY plane of AxisSystem18 | ZX plane of AxisSystem18]
    reference projected line E2 through (0, 0) direction (-1, 0) from edge [XY plane of AxisSystem18 | ZX plane of AxisSystem18]
    reference projected line E3 through (0, 0) direction (0, 1) from edge [ZX plane of AxisSystem18 | YZ plane of AxisSystem18]
    point P7 (-7.08, 0)
    construction line L9 (-11.04, 3.96) -> (-7.08, 0)
    reference projected line E4 through (0, 0) direction (-1, 0) from edge [XY plane of AxisSystem18 | ZX plane of AxisSystem18]
    line L10 (5.08, -10.414) -> (5.08, -2)
    line L11 (3.5687, -10.414) -> (5.08, -10.414)
    arc A1 centre (5.08, -10.414) radius 0 from (5.08, -10.414) to (5.08, -10.414) ccw
    point P9 (5.08, -10.414)
    reference projected line E5 through (0, 0) direction (-1, 0) from edge [XY plane of AxisSystem18 | ZX plane of AxisSystem18]
    construction line L12 (5.08, -10.414) -> (5.08, -10.414)
    construction line L13 (5.08, -10.414) -> (5.08, -10.414)
    point P10 (5.08, -10.414)
    point P11 (5.08, -10.414)
    point P12 (5.08, -10.414)
    line L14 (3.5687, -40.64) -> (3.5687, -40.64)
    point P13 (3.5687, -40.64)
    point P14 (-3.5687, -40.64)
    point P15 (-3.5687, -40.64)
    construction line L15 (-3.5687, -40.64) -> (-3.5687, -40.64)
    point P18 (5.08, -2)
    reference projected line E6 through (0, 0) direction (-1, 0) from edge [XY plane of AxisSystem18 | ZX plane of AxisSystem18]
    point P19 (0, 30)
    angle L4 L9 = 90
    radius about axis L1 L3 = 3.5687 {= Body5.DB / 2}
    distance E1 L2 = 40.64 {= Body5.Offset + (Sketch29.length(L2) * (Body5.Offset / Body5.Offset))}
    length L8 = 7.08 {= sqrt((Body5.AS_H * Body5.AS_H ) + ((Groove5.top_width / 2 + Groove5.AS_ZR ) * (Groove5.top_width / 2 + Groove5.AS_ZR )))}
    angle L8 L5 = 0 {= atan(Body5.AS_H / (Groove5.top_width / 2 + Groove5.AS_ZR ))}
    distance E6 P18 = 2 (reference)
    distance L5 L11 = 10.414
    radius about axis L10 L1 = 5.08 {= Body5.DFS / 2}
    distance E5 P9 = 10.414 {= Body5.TFS - Body5.R}
    radius about axis P9 L1 = 5.08 {= (Body5.DFS / 2) - Body5.R}
    radius A1 = 0 (reference)
    angle L14 L15 = 0
    distance L2 P3 = 0
    length L2 = 3.5687 (reference)
    distance O P19 = 30
    distance P18 P19 V = 32 {= Sketch29.distance(O P19) + Body5.F1}
    coincidence: E4 L5, L1 E3, P11 P10, P12 L11, P19 L1
    perpendicularity: L1 L7, E2 L6, L12 L10, L13 L11
    symmetry: P4 P7 L1, L4 L9 L1, P3 P14 L1, P13 P15 L1, L14 L15 L1
  Groove5 "MainGroove": profile Sketch29, axis Sketch29.L1, angle 360
  Point22 "LimitingAxisSystemOrigin": type OnCurve, Support edge [ZX plane of AxisSystem18 | YZ plane of AxisSystem18], RefPoint Intersect4, Length 0 {= (Sketch29.length(L2)) * (Body5.Offset / Body5.Offset)}
  AxisSystem19 "LimitingAxisSystem": origin (-108.585, 50.8, -209.55), X (-0.9916, -0.1291, 0), Y (0.1168, -0.8972, -0.4259), Z (0.055, -0.4224, 0.9048)
Relations
  Body2.W1 = Sketch26.angle(L4 L9)
  Body2.W3 = Sketch26.angle(L14 L15)
  Body2.TFS = Sketch26.distance(L5 L11)
  Body2.T = Sketch26.distance(E1 L2)
  Body2.F3 = Sketch26.distance(L2 P3)
  Groove2.top_width = (`Sketch26.radius about axis(L10 L1)` * 2) + (2 * tan(Sketch26.angle(L4 L9) / 2) * Sketch26.distance(E6 P18) )
  rule "AS_ZR":
    /*Rule created by AKNOPP 22.05.2006*/
    Groove2.AS_ZR = Body2.AS_D - Groove2.top_width
    if (Body2.AS_D == 0mm)
    {
    	Groove2.AS_ZR = 0mm
    }
    else
    {
    	Groove2.AS_ZR = (Body2.AS_D / 2) - (Groove2.top_width / 2)
    }
  Body3.W1 = Sketch27.angle(L4 L9)
  Body3.W3 = Sketch27.angle(L14 L15)
  Body3.TFS = Sketch27.distance(L5 L11)
  Body3.T = Sketch27.distance(E1 L2)
  Body3.F3 = Sketch27.distance(L2 P3)
  Groove3.top_width = (`Sketch27.radius about axis(L10 L1)` * 2) + (2 * tan(Sketch27.angle(L4 L9) / 2) * Sketch27.distance(E6 P18) )
  rule "AS_ZR":
    /*Rule created by AKNOPP 22.05.2006*/
    Groove3.AS_ZR = Body3.AS_D - Groove3.top_width
    if (Body3.AS_D == 0mm)
    {
    	Groove3.AS_ZR = 0mm
    }
    else
    {
    	Groove3.AS_ZR = (Body3.AS_D / 2) - (Groove3.top_width / 2)
    }
  Body4.W1 = Sketch28.angle(L4 L9)
  Body4.W3 = Sketch28.angle(L14 L15)
  Body4.TFS = Sketch28.distance(L5 L11)
  Body4.T = Sketch28.distance(E1 L2)
  Body4.F3 = Sketch28.distance(L2 P3)
  Groove4.top_width = (`Sketch28.radius about axis(L10 L1)` * 2) + (2 * tan(Sketch28.angle(L4 L9) / 2) * Sketch28.distance(E6 P18) )
  rule "AS_ZR":
    /*Rule created by AKNOPP 22.05.2006*/
    Groove4.AS_ZR = Body4.AS_D - Groove4.top_width
    if (Body4.AS_D == 0mm)
    {
    	Groove4.AS_ZR = 0mm
    }
    else
    {
    	Groove4.AS_ZR = (Body4.AS_D / 2) - (Groove4.top_width / 2)
    }
  Body5.W1 = Sketch29.angle(L4 L9)
  Body5.W3 = Sketch29.angle(L14 L15)
  Body5.TFS = Sketch29.distance(L5 L11)
  Body5.T = Sketch29.distance(E1 L2)
  Body5.F3 = Sketch29.distance(L2 P3)
  Groove5.top_width = (`Sketch29.radius about axis(L10 L1)` * 2) + (2 * tan(Sketch29.angle(L4 L9) / 2) * Sketch29.distance(E6 P18) )
  rule "AS_ZR":
    /*Rule created by AKNOPP 22.05.2006*/
    Groove5.AS_ZR = Body5.AS_D - Groove5.top_width
    if (Body5.AS_D == 0mm)
    {
    	Groove5.AS_ZR = 0mm
    }
    else
    {
    	Groove5.AS_ZR = (Body5.AS_D / 2) - (Groove5.top_width / 2)
    }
